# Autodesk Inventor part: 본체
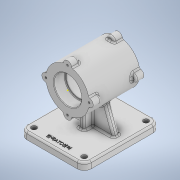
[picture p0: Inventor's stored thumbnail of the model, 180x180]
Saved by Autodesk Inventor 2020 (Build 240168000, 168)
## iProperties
Created: 2022-11
Part Number: 본체
Material: 일반
Document SubType Name: Modeling
Designer: owner
Density: 1 g/cm^3
Appearance: 기본값
Mass: 450.145 g
Surface Area: 796.917 cm^2
Volume: 450.145 cm^3
Author: owner
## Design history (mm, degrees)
sketch "스케치1"
  geometry: C1 r 37 at (0, 0); 1 further point
  constraints: 1 centre point, 1 coincident
  dimensions: "d0" = 74 diameter of C1
extrude "돌출1" new body sketch "스케치1" stored distance "d6" = 87; taper "d7" = 0 deg
sketch "스케치2"
  geometry: A1 r 37 centre (0, 0) between (36.338, 6.969) and (6.969, 36.338) reference; 2 further points
  constraints: 1 coincident
hole "구멍1" sketch "스케치2" at (0, 0) diameter "d8" = 42; stored, may be unused: countersink angle "d12" = 90 deg, drill point angle "d14" = 0 deg; dims "d9" = 8, "d10" = 47, "d11" = 19, "d13" = 10
sketch "스케치3"
  geometry: A1 r 37 centre (0, 0) between (36.338, 6.969) and (6.969, 36.338) reference; 2 further points
  constraints: 1 coincident
hole "구멍2" sketch "스케치3" at (0, 0) diameter "d15" = 42; stored, may be unused: countersink angle "d19" = 90 deg, drill point angle "d21" = 0 deg; dims "d16" = 8, "d17" = 47, "d18" = 19, "d20" = 10
node "작업 평면1"
sketch "스케치4"
  geometry: L1 (-55, 70)-(55, 70); L2 (55, 70)-(55, -60); L3 (55, -60)-(-55, -60); L4 (-55, -60)-(-55, 70); 2 further points
  constraints: 8 end point, 2 parallel, 1 horizontal, 1 midpoint, 1 perpendicular, 1 vertical alignment
  dimensions: "d23" = 110 distance of L2.end L3.end; "d24" = 130 distance of L1.end L2.end; "d25" = 70 distance from line of point (0, 0) L1
extrude "돌출2" join sketch "스케치4" distance "d26" = 12; taper "d27" = 0 deg
node "작업 평면2"
sketch "스케치5"
  geometry: L1 (14, 12)-(29.664, 55.036); L2 (110, 12)-(0, 12) reference; L3 (96, 12)-(80.336, 55.036); A1 r 37 centre (55, 82) between (29.664, 55.036) and (18.662, 75.031) reference; A2 r 37 centre (55, 82) between (80.336, 55.036) and (61.969, 45.662) reference; 4 further points
  constraints: 4 end point, 2 point on circle, 2 point on line, 1 equal length
  dimensions: "d29" = 14 distance of L1.start L2.end; "d30" = 14 distance of L3.start L2.start; "d31" = 110 deg angle of L2 L3
extrude "돌출3" join sketch "스케치5" stored distance "d32" = 10; taper "d33" = 0 deg
sketch "스케치6"
  geometry: C1 r 7 at (0, 37); C2 r 7 at (-37, 0); C3 r 7 at (0, -37); C4 r 7 at (37, 0); 10 further points
  constraints: 4 centre point, 1 vertical alignment, 11 other
  dimensions: "d34" = 14 diameter of C1; "d37" = 360 deg dimension on point (0, 0) C1.centre (derived)
extrude "돌출4" join sketch "스케치6" distance "d39" = 14; taper "d40" = 0 deg
sketch "스케치7"
  geometry: L1 (-70, -60)-(-70, 70) reference; L2 (-70, 20)-(-37, 20); L3 (-70, -20)-(-37, -20); L4 (-37, -43.5)-(-37, 29.5) reference; 1 further point
  constraints: 4 end point, 4 point on line, 2 horizontal
  dimensions: "d41" = 20 distance from line of L3 point (0, 0); "d42" = 40 distance between parallel lines of L2 L3
feature "리브1" sketch "스케치7" dims "d43" = 1, "d44" = 10, "d45" = 0, "d46" = 0, "d47" = 1, "d48" = 1
fillet "모깎기1" dims "d49" = 12
fillet "모깎기2" dims "d50" = 3
fillet "모깎기3" dims "d51" = 3
sketch "스케치8"
  geometry: A1 r 12 centre (-43, 48) between (-43, 60) and (-55, 48) reference; 2 further points
  constraints: 1 coincident
hole "구멍3" sketch "스케치8" at (-43, 48) diameter "d52" = 9; stored, may be unused: countersink angle "d56" = 90 deg, drill point angle "d58" = 0 deg; dims "d53" = 8, "d54" = 47, "d55" = 19, "d57" = 10
sketch "스케치9"
  geometry: A1 r 12 centre (-43, -58) between (-55, -58) and (-43, -70) reference; 2 further points
  constraints: 1 coincident
hole "구멍4" sketch "스케치9" at (-43, -58) diameter "d59" = 9; stored, may be unused: countersink angle "d63" = 90 deg, drill point angle "d65" = 0 deg; dims "d60" = 8, "d61" = 47, "d62" = 19, "d64" = 10
sketch "스케치10"
  geometry: A1 r 12 centre (43, -58) between (43, -70) and (55, -58) reference; 2 further points
  constraints: 1 coincident
hole "구멍5" sketch "스케치10" at (43, -58) diameter "d66" = 9; stored, may be unused: countersink angle "d70" = 90 deg, drill point angle "d72" = 0 deg; dims "d67" = 8, "d68" = 47, "d69" = 19, "d71" = 10
sketch "스케치11"
  geometry: A1 r 12 centre (43, 48) between (55, 48) and (43, 60) reference; 2 further points
  constraints: 1 coincident
hole "구멍6" sketch "스케치11" at (43, 48) diameter "d73" = 9; stored, may be unused: countersink angle "d77" = 90 deg, drill point angle "d79" = 0 deg; dims "d74" = 8, "d75" = 47, "d76" = 19, "d78" = 10
sketch "스케치12"
  geometry: 1 further point
sketch "스케치13"
  geometry: A1 r 7 centre (0, 37) between (6.889, 38.239) and (-6.889, 38.239) reference; 2 further points
  constraints: 1 coincident
hole "구멍7" sketch "스케치13" at (0, 37) diameter "d80" = 3.242; stored, may be unused: countersink angle "d84" = 90 deg, drill point angle "d86" = 118 deg; dims "d81" = 8, "d82" = 47, "d83" = 19, "d85" = 10
fillet "모깎기4" dims "d90" = 3
fillet "모깎기5" dims "d91" = 3
fillet "모깎기6" dims "d92" = 3
chamfer "모따기1" distance "d93" = 1; stored, may be unused: second distance "d94" = 2, angle "d95" = 45 deg
fillet "모깎기7" dims "d96" = 1
sketch "스케치14"
  geometry: L1 (-43, -70)-(43, -70) reference; 2 further points
  constraints: 1 vertical alignment, 1 other
  dimensions: "d97" = 12 distance from line of L1 point (0, -58)
feature "엠보싱1" sketch "스케치14" dims "d6" = 87, "d23" = 110, "d24" = 130, "d25" = 70, "d98" = 0.5, "d99" = 0
node "솔리드1"
mirror "미러2"
pattern_circular "원형 패턴1" dims angle "d88" = 360 deg
mirror "미러4"
mirror "미러5"
feature "A9D066F2-1C7D-4E18-AEED-F7BC21143FA4" dims "d8" = 42, "d9" = 8, "d10" = 47, "d11" = 19, "d12" = 90 deg, "d13" = 10, "d14" = 0
other parameters: "d22" = -82
